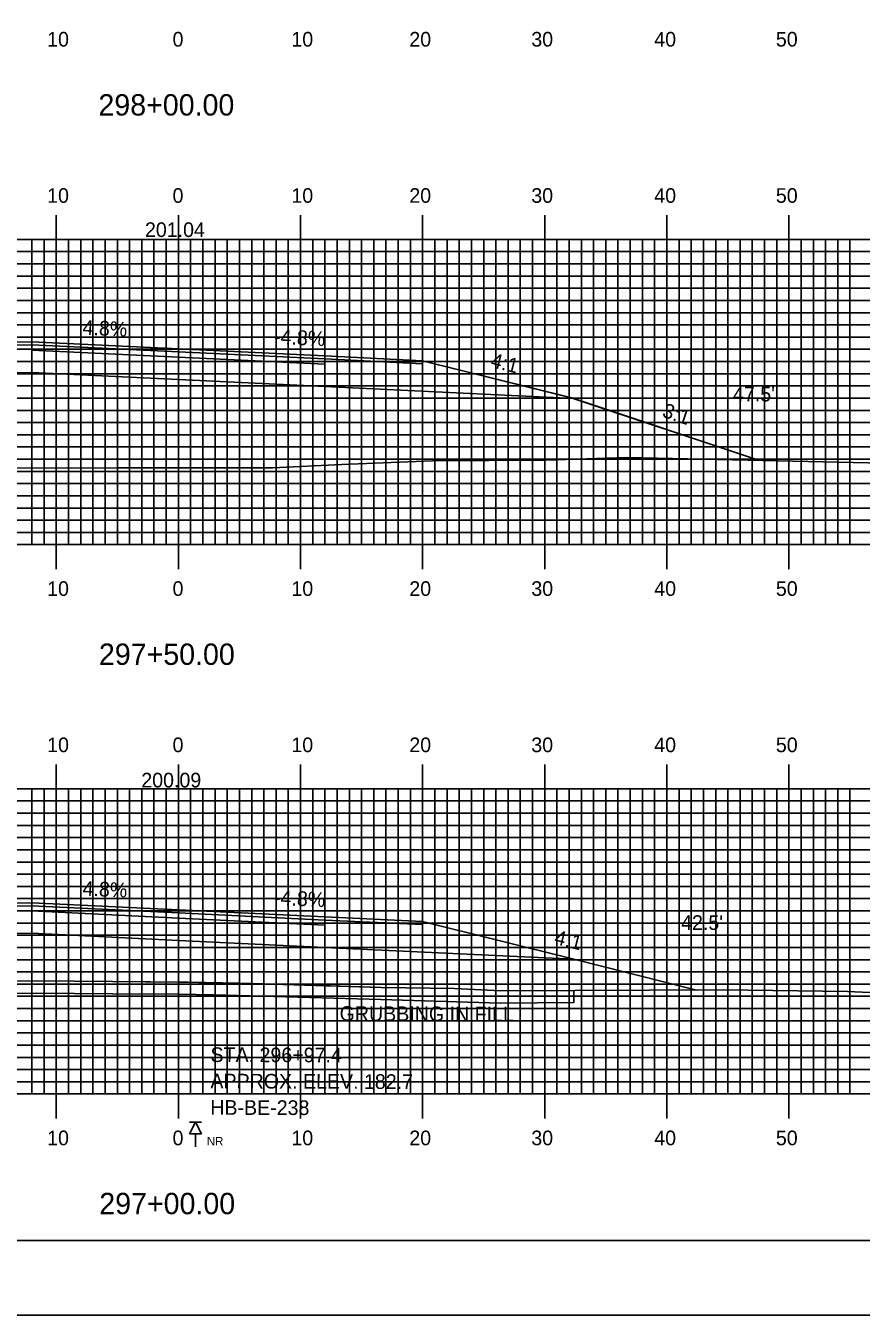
# Model space of a CAD drawing. Extents: x 1814915 to 1815259, y 442591 to 442811.
# Drawn here: x 1815068.5 to 1815136.9, y 442590.5 to 442696.2 of the extents above; entities that cross this region are included whole.
import ezdxf

# ---------------------------------------------------------------- set-up
doc = ezdxf.new("R2010")
doc.units = 0
for name, color, linetype in [('ANNOTATION', 7, 'Continuous'), ('BORDER', 7, 'Continuous'), ('BORING - NO REFUSAL', 7, 'Continuous'), ('D_Roadway_Centerline', 7, 'Continuous'), ('D_Roadway_Centerline_Text', 7, 'Continuous'), ('D_Roadway_Edge_Shoulder', 7, 'Continuous'), ('D_Roadway_Edge_TW', 7, 'Continuous'), ('D_Roadway_Pavement', 7, 'Continuous'), ('D_Roadway_SlopeLines', 7, 'Continuous'), ('D_Roadway_SubGrade', 7, 'Continuous'), ('D_Text_Standard', 7, 'Continuous'), ('GRUBBING IN FILL', 7, 'Continuous'), ('H_V ANNOTATION', 7, 'Continuous'), ('MAJOR', 7, 'Continuous'), ('MINOR', 7, 'Continuous'), ('PLOT BOUNDARY', 7, 'Continuous'), ('S_Roadway_Centerline', 7, 'Continuous')]:
    doc.layers.add(name, color=color, linetype=linetype)

msp = doc.modelspace()

# ---------------------------------------------------------------- linework, layer by layer
at = {"layer": 'BORDER'}
msp.add_lwpolyline([(1814931.42, 442596.67), (1815251.42, 442596.67), (1815251.42, 442806.67), (1814931.42, 442806.67)], close=True, dxfattribs=at)
at = {"layer": 'BORING - NO REFUSAL'}
for p, q in [((1815082.9, 442606.37), (1815081.94, 442606.37)), ((1815082.42, 442605.41), (1815082.42, 442604.35))]:
    msp.add_line(p, q, dxfattribs=at)
msp.add_lwpolyline([(1815082.42, 442606.37), (1815082.9, 442605.41), (1815081.94, 442605.41)], close=True, dxfattribs=at)
at = {"layer": 'D_Roadway_Centerline'}
for points in [[(1815026.39, 442659.58), (1815049.02, 442667.12), (1815050.15, 442667.4), (1815061.02, 442670.12), (1815069.02, 442670.28), (1815081.02, 442669.7), (1815093.02, 442669.13), (1815101.02, 442668.74), (1815113.02, 442665.74), (1815113.4, 442665.65), (1815128.52, 442660.58)], [(1815032.71, 442617.09), (1815049.02, 442621.17), (1815050.15, 442621.45), (1815061.02, 442624.17), (1815069.02, 442624.33), (1815081.02, 442623.75), (1815093.02, 442623.17), (1815101.02, 442622.79), (1815113.4, 442619.7), (1815123.45, 442617.18)]]:
    msp.add_lwpolyline(points, dxfattribs=at)
at = {"layer": 'D_Roadway_Edge_Shoulder'}
for points in [[(1815069.02, 442670.28), (1815061.02, 442670.12), (1815061.02, 442669.87), (1815069.02, 442670.03)], [(1815093.02, 442669.13), (1815101.02, 442668.74), (1815101.02, 442668.49), (1815093.02, 442668.88)], [(1815069.02, 442624.33), (1815061.02, 442624.17), (1815061.02, 442623.92), (1815069.02, 442624.08)], [(1815093.02, 442623.17), (1815101.02, 442622.79), (1815101.02, 442622.54), (1815093.02, 442622.92)]]:
    msp.add_lwpolyline(points, close=True, dxfattribs=at)
at = {"layer": 'D_Roadway_Edge_TW'}
for points in [[(1815069.02, 442670.03), (1815069.02, 442670.28), (1815081.02, 442669.7), (1815093.02, 442669.13), (1815093.02, 442668.88), (1815081.02, 442669.45)], [(1815069.02, 442624.08), (1815069.02, 442624.33), (1815081.02, 442623.75), (1815093.02, 442623.17), (1815093.02, 442622.92), (1815081.02, 442623.5)]]:
    msp.add_lwpolyline(points, close=True, dxfattribs=at)
at = {"layer": 'D_Roadway_Pavement'}
for points in [[(1815069.02, 442669.61), (1815069.02, 442670.03), (1815081.02, 442669.45), (1815093.02, 442668.88), (1815093.02, 442668.46), (1815081.02, 442669.04)], [(1815069.02, 442623.66), (1815069.02, 442624.08), (1815081.02, 442623.5), (1815093.02, 442622.92), (1815093.02, 442622.51), (1815081.02, 442623.08)]]:
    msp.add_lwpolyline(points, close=True, dxfattribs=at)
at = {"layer": 'D_Roadway_SlopeLines'}
for points in [[(1815101.02, 442668.74), (1815113.02, 442665.74), (1815128.52, 442660.58)], [(1815101.02, 442622.79), (1815113.4, 442619.7), (1815123.45, 442617.18)]]:
    msp.add_lwpolyline(points, dxfattribs=at)
at = {"layer": 'D_Roadway_SubGrade'}
for points in [[(1815069.02, 442667.78), (1815050.15, 442667.4), (1815061.02, 442670.12), (1815061.02, 442669.87), (1815069.02, 442670.03), (1815081.02, 442669.45), (1815093.02, 442668.88), (1815101.02, 442668.49), (1815101.02, 442668.74), (1815113.4, 442665.65), (1815093.02, 442666.63), (1815081.02, 442667.2)], [(1815069.02, 442621.83), (1815050.15, 442621.45), (1815061.02, 442624.17), (1815061.02, 442623.92), (1815069.02, 442624.08), (1815081.02, 442623.5), (1815093.02, 442622.92), (1815101.02, 442622.54), (1815101.02, 442622.79), (1815113.4, 442619.7), (1815093.02, 442620.67), (1815081.02, 442621.25)]]:
    msp.add_lwpolyline(points, close=True, dxfattribs=at)
at = {"layer": 'GRUBBING IN FILL'}
for points in [[(1815050.15, 442617.63), (1815052.24, 442617.71), (1815056.96, 442617.81), (1815064.58, 442617.9), (1815069.39, 442617.94), (1815075.61, 442617.88), (1815081.02, 442617.84), (1815081.02, 442616.84), (1815075.61, 442616.88), (1815069.39, 442616.94), (1815064.59, 442616.9), (1815056.98, 442616.81), (1815053.08, 442616.75), (1815050.15, 442616.59)], [(1815050.15, 442617.63), (1815052.24, 442617.71), (1815056.96, 442617.81), (1815064.58, 442617.9), (1815069.39, 442617.94), (1815075.61, 442617.88), (1815081.02, 442617.84), (1815081.02, 442616.84), (1815075.61, 442616.88), (1815069.39, 442616.94), (1815064.59, 442616.9), (1815056.98, 442616.81), (1815053.08, 442616.75), (1815050.15, 442616.59)], [(1815081.02, 442617.84), (1815086, 442617.75), (1815091.82, 442617.57), (1815097.63, 442617.4), (1815103.62, 442617.3), (1815107.42, 442617.12), (1815113.4, 442617.15), (1815113.4, 442616.15), (1815107.4, 442616.12), (1815097.61, 442616.4), (1815091.79, 442616.57), (1815083.9, 442616.79), (1815081.02, 442616.84)], [(1815081.02, 442617.84), (1815086, 442617.75), (1815091.82, 442617.57), (1815097.63, 442617.4), (1815103.62, 442617.3), (1815107.42, 442617.12), (1815113.4, 442617.15), (1815113.4, 442616.15), (1815107.4, 442616.12), (1815097.61, 442616.4), (1815091.79, 442616.57), (1815083.9, 442616.79), (1815081.02, 442616.84)]]:
    msp.add_lwpolyline(points, close=True, dxfattribs=at)
at = {"layer": 'MAJOR'}
for p, q in [((1815071.02, 442680.67), (1815071.02, 442678.67)), ((1815081.02, 442680.67), (1815081.02, 442678.67)), ((1815091.02, 442680.67), (1815091.02, 442678.67)), ((1815101.02, 442680.67), (1815101.02, 442678.67)), ((1815111.02, 442680.67), (1815111.02, 442678.67)), ((1815121.02, 442680.67), (1815121.02, 442678.67)), ((1815131.02, 442680.67), (1815131.02, 442678.67)), ((1814941.02, 442678.67), (1815221.02, 442678.67)), ((1814941.02, 442678.67), (1815221.02, 442678.67)), ((1815071.02, 442653.67), (1815071.02, 442678.67)), ((1815081.02, 442653.67), (1815081.02, 442678.67)), ((1815091.02, 442653.67), (1815091.02, 442678.67)), ((1815101.02, 442653.67), (1815101.02, 442678.67)), ((1815111.02, 442653.67), (1815111.02, 442678.67)), ((1815121.02, 442653.67), (1815121.02, 442678.67)), ((1815131.02, 442653.67), (1815131.02, 442678.67)), ((1814941.02, 442673.67), (1815221.02, 442673.67)), ((1814941.02, 442668.67), (1815221.02, 442668.67)), ((1814941.02, 442663.67), (1815221.02, 442663.67)), ((1814941.02, 442658.67), (1815221.02, 442658.67)), ((1814941.02, 442653.67), (1815221.02, 442653.67)), ((1814941.02, 442653.67), (1815221.02, 442653.67)), ((1815071.02, 442651.66), (1815071.02, 442653.67)), ((1815081.02, 442651.66), (1815081.02, 442653.67)), ((1815091.02, 442651.66), (1815091.02, 442653.67)), ((1815101.02, 442651.66), (1815101.02, 442653.67)), ((1815111.02, 442651.66), (1815111.02, 442653.67)), ((1815121.02, 442651.66), (1815121.02, 442653.67)), ((1815131.02, 442651.66), (1815131.02, 442653.67)), ((1815071.02, 442635.67), (1815071.02, 442633.67)), ((1815081.02, 442635.67), (1815081.02, 442633.67)), ((1815091.02, 442635.67), (1815091.02, 442633.67)), ((1815101.02, 442635.67), (1815101.02, 442633.67)), ((1815111.02, 442635.67), (1815111.02, 442633.67)), ((1815121.02, 442635.67), (1815121.02, 442633.67)), ((1815131.02, 442635.67), (1815131.02, 442633.67)), ((1814941.02, 442633.67), (1815221.02, 442633.67)), ((1814941.02, 442633.67), (1815221.02, 442633.67)), ((1815071.02, 442608.67), (1815071.02, 442633.67)), ((1815081.02, 442608.67), (1815081.02, 442633.67)), ((1815091.02, 442608.67), (1815091.02, 442633.67)), ((1815101.02, 442608.67), (1815101.02, 442633.67)), ((1815111.02, 442608.67), (1815111.02, 442633.67)), ((1815121.02, 442608.67), (1815121.02, 442633.67)), ((1815131.02, 442608.67), (1815131.02, 442633.67)), ((1814941.02, 442628.67), (1815221.02, 442628.67)), ((1814941.02, 442623.67), (1815221.02, 442623.67)), ((1814941.02, 442618.67), (1815221.02, 442618.67)), ((1814941.02, 442613.67), (1815221.02, 442613.67)), ((1814941.02, 442608.67), (1815221.02, 442608.67)), ((1814941.02, 442608.67), (1815221.02, 442608.67)), ((1815071.02, 442606.66), (1815071.02, 442608.67)), ((1815081.02, 442606.66), (1815081.02, 442608.67)), ((1815091.02, 442606.66), (1815091.02, 442608.67)), ((1815101.02, 442606.66), (1815101.02, 442608.67)), ((1815111.02, 442606.66), (1815111.02, 442608.67)), ((1815121.02, 442606.66), (1815121.02, 442608.67)), ((1815131.02, 442606.66), (1815131.02, 442608.67))]:
    msp.add_line(p, q, dxfattribs=at)
at = {"layer": 'MINOR'}
for p, q in [((1815069.02, 442653.67), (1815069.02, 442678.67)), ((1815070.02, 442653.67), (1815070.02, 442678.67)), ((1815072.02, 442653.67), (1815072.02, 442678.67)), ((1815073.02, 442653.67), (1815073.02, 442678.67)), ((1815074.02, 442653.67), (1815074.02, 442678.67)), ((1815075.02, 442653.67), (1815075.02, 442678.67)), ((1815076.02, 442653.67), (1815076.02, 442678.67)), ((1815077.02, 442653.67), (1815077.02, 442678.67)), ((1815078.02, 442653.67), (1815078.02, 442678.67)), ((1815079.02, 442653.67), (1815079.02, 442678.67)), ((1815080.02, 442653.67), (1815080.02, 442678.67)), ((1815082.02, 442653.67), (1815082.02, 442678.67)), ((1815083.02, 442653.67), (1815083.02, 442678.67)), ((1815084.02, 442653.67), (1815084.02, 442678.67)), ((1815085.02, 442653.67), (1815085.02, 442678.67)), ((1815086.02, 442653.67), (1815086.02, 442678.67)), ((1815087.02, 442653.67), (1815087.02, 442678.67)), ((1815088.02, 442653.67), (1815088.02, 442678.67)), ((1815089.02, 442653.67), (1815089.02, 442678.67)), ((1815090.02, 442653.67), (1815090.02, 442678.67)), ((1815092.02, 442653.67), (1815092.02, 442678.67)), ((1815093.02, 442653.67), (1815093.02, 442678.67)), ((1815094.02, 442653.67), (1815094.02, 442678.67)), ((1815095.02, 442653.67), (1815095.02, 442678.67)), ((1815096.02, 442653.67), (1815096.02, 442678.67)), ((1815097.02, 442653.67), (1815097.02, 442678.67)), ((1815098.02, 442653.67), (1815098.02, 442678.67)), ((1815099.02, 442653.67), (1815099.02, 442678.67)), ((1815100.02, 442653.67), (1815100.02, 442678.67)), ((1815102.02, 442653.67), (1815102.02, 442678.67)), ((1815103.02, 442653.67), (1815103.02, 442678.67)), ((1815104.02, 442653.67), (1815104.02, 442678.67)), ((1815105.02, 442653.67), (1815105.02, 442678.67)), ((1815106.02, 442653.67), (1815106.02, 442678.67)), ((1815107.02, 442653.67), (1815107.02, 442678.67)), ((1815108.02, 442653.67), (1815108.02, 442678.67)), ((1815109.02, 442653.67), (1815109.02, 442678.67)), ((1815110.02, 442653.67), (1815110.02, 442678.67)), ((1815112.02, 442653.67), (1815112.02, 442678.67)), ((1815113.02, 442653.67), (1815113.02, 442678.67)), ((1815114.02, 442653.67), (1815114.02, 442678.67)), ((1815115.02, 442653.67), (1815115.02, 442678.67)), ((1815116.02, 442653.67), (1815116.02, 442678.67)), ((1815117.02, 442653.67), (1815117.02, 442678.67)), ((1815118.02, 442653.67), (1815118.02, 442678.67)), ((1815119.02, 442653.67), (1815119.02, 442678.67)), ((1815120.02, 442653.67), (1815120.02, 442678.67)), ((1815122.02, 442653.67), (1815122.02, 442678.67)), ((1815123.02, 442653.67), (1815123.02, 442678.67)), ((1815124.02, 442653.67), (1815124.02, 442678.67)), ((1815125.02, 442653.67), (1815125.02, 442678.67)), ((1815126.02, 442653.67), (1815126.02, 442678.67)), ((1815127.02, 442653.67), (1815127.02, 442678.67)), ((1815128.02, 442653.67), (1815128.02, 442678.67)), ((1815129.02, 442653.67), (1815129.02, 442678.67)), ((1815130.02, 442653.67), (1815130.02, 442678.67)), ((1815132.02, 442653.67), (1815132.02, 442678.67)), ((1815133.02, 442653.67), (1815133.02, 442678.67)), ((1815134.02, 442653.67), (1815134.02, 442678.67)), ((1815135.02, 442653.67), (1815135.02, 442678.67)), ((1815136.02, 442653.67), (1815136.02, 442678.67)), ((1814941.02, 442677.67), (1815221.02, 442677.67)), ((1814941.02, 442676.67), (1815221.02, 442676.67)), ((1814941.02, 442675.67), (1815221.02, 442675.67)), ((1814941.02, 442674.67), (1815221.02, 442674.67)), ((1814941.02, 442672.67), (1815221.02, 442672.67)), ((1814941.02, 442671.67), (1815221.02, 442671.67)), ((1814941.02, 442670.67), (1815221.02, 442670.67)), ((1814941.02, 442669.67), (1815221.02, 442669.67)), ((1814941.02, 442667.67), (1815221.02, 442667.67)), ((1814941.02, 442666.67), (1815221.02, 442666.67)), ((1814941.02, 442665.67), (1815221.02, 442665.67)), ((1814941.02, 442664.67), (1815221.02, 442664.67)), ((1814941.02, 442662.67), (1815221.02, 442662.67)), ((1814941.02, 442661.67), (1815221.02, 442661.67)), ((1814941.02, 442660.67), (1815221.02, 442660.67)), ((1814941.02, 442659.67), (1815221.02, 442659.67)), ((1814941.02, 442657.67), (1815221.02, 442657.67)), ((1814941.02, 442656.67), (1815221.02, 442656.67)), ((1814941.02, 442655.67), (1815221.02, 442655.67)), ((1814941.02, 442654.67), (1815221.02, 442654.67)), ((1815069.02, 442608.67), (1815069.02, 442633.67)), ((1815070.02, 442608.67), (1815070.02, 442633.67)), ((1815072.02, 442608.67), (1815072.02, 442633.67)), ((1815073.02, 442608.67), (1815073.02, 442633.67)), ((1815074.02, 442608.67), (1815074.02, 442633.67)), ((1815075.02, 442608.67), (1815075.02, 442633.67)), ((1815076.02, 442608.67), (1815076.02, 442633.67)), ((1815077.02, 442608.67), (1815077.02, 442633.67)), ((1815078.02, 442608.67), (1815078.02, 442633.67)), ((1815079.02, 442608.67), (1815079.02, 442633.67)), ((1815080.02, 442608.67), (1815080.02, 442633.67)), ((1815082.02, 442608.67), (1815082.02, 442633.67)), ((1815083.02, 442608.67), (1815083.02, 442633.67)), ((1815084.02, 442608.67), (1815084.02, 442633.67)), ((1815085.02, 442608.67), (1815085.02, 442633.67)), ((1815086.02, 442608.67), (1815086.02, 442633.67)), ((1815087.02, 442608.67), (1815087.02, 442633.67)), ((1815088.02, 442608.67), (1815088.02, 442633.67)), ((1815089.02, 442608.67), (1815089.02, 442633.67)), ((1815090.02, 442608.67), (1815090.02, 442633.67)), ((1815092.02, 442608.67), (1815092.02, 442633.67)), ((1815093.02, 442608.67), (1815093.02, 442633.67)), ((1815094.02, 442608.67), (1815094.02, 442633.67)), ((1815095.02, 442608.67), (1815095.02, 442633.67)), ((1815096.02, 442608.67), (1815096.02, 442633.67)), ((1815097.02, 442608.67), (1815097.02, 442633.67)), ((1815098.02, 442608.67), (1815098.02, 442633.67)), ((1815099.02, 442608.67), (1815099.02, 442633.67)), ((1815100.02, 442608.67), (1815100.02, 442633.67)), ((1815102.02, 442608.67), (1815102.02, 442633.67)), ((1815103.02, 442608.67), (1815103.02, 442633.67)), ((1815104.02, 442608.67), (1815104.02, 442633.67)), ((1815105.02, 442608.67), (1815105.02, 442633.67)), ((1815106.02, 442608.67), (1815106.02, 442633.67)), ((1815107.02, 442608.67), (1815107.02, 442633.67)), ((1815108.02, 442608.67), (1815108.02, 442633.67)), ((1815109.02, 442608.67), (1815109.02, 442633.67)), ((1815110.02, 442608.67), (1815110.02, 442633.67)), ((1815112.02, 442608.67), (1815112.02, 442633.67)), ((1815113.02, 442608.67), (1815113.02, 442633.67)), ((1815114.02, 442608.67), (1815114.02, 442633.67)), ((1815115.02, 442608.67), (1815115.02, 442633.67)), ((1815116.02, 442608.67), (1815116.02, 442633.67)), ((1815117.02, 442608.67), (1815117.02, 442633.67)), ((1815118.02, 442608.67), (1815118.02, 442633.67)), ((1815119.02, 442608.67), (1815119.02, 442633.67)), ((1815120.02, 442608.67), (1815120.02, 442633.67)), ((1815122.02, 442608.67), (1815122.02, 442633.67)), ((1815123.02, 442608.67), (1815123.02, 442633.67)), ((1815124.02, 442608.67), (1815124.02, 442633.67)), ((1815125.02, 442608.67), (1815125.02, 442633.67)), ((1815126.02, 442608.67), (1815126.02, 442633.67)), ((1815127.02, 442608.67), (1815127.02, 442633.67)), ((1815128.02, 442608.67), (1815128.02, 442633.67)), ((1815129.02, 442608.67), (1815129.02, 442633.67)), ((1815130.02, 442608.67), (1815130.02, 442633.67)), ((1815132.02, 442608.67), (1815132.02, 442633.67)), ((1815133.02, 442608.67), (1815133.02, 442633.67)), ((1815134.02, 442608.67), (1815134.02, 442633.67)), ((1815135.02, 442608.67), (1815135.02, 442633.67)), ((1815136.02, 442608.67), (1815136.02, 442633.67)), ((1814941.02, 442632.67), (1815221.02, 442632.67)), ((1814941.02, 442631.67), (1815221.02, 442631.67)), ((1814941.02, 442630.67), (1815221.02, 442630.67)), ((1814941.02, 442629.67), (1815221.02, 442629.67)), ((1814941.02, 442627.67), (1815221.02, 442627.67)), ((1814941.02, 442626.67), (1815221.02, 442626.67)), ((1814941.02, 442625.67), (1815221.02, 442625.67)), ((1814941.02, 442624.67), (1815221.02, 442624.67)), ((1814941.02, 442622.67), (1815221.02, 442622.67)), ((1814941.02, 442621.67), (1815221.02, 442621.67)), ((1814941.02, 442620.67), (1815221.02, 442620.67)), ((1814941.02, 442619.67), (1815221.02, 442619.67)), ((1814941.02, 442617.67), (1815221.02, 442617.67)), ((1814941.02, 442616.67), (1815221.02, 442616.67)), ((1814941.02, 442615.67), (1815221.02, 442615.67)), ((1814941.02, 442614.67), (1815221.02, 442614.67)), ((1814941.02, 442612.67), (1815221.02, 442612.67)), ((1814941.02, 442611.67), (1815221.02, 442611.67)), ((1814941.02, 442610.67), (1815221.02, 442610.67)), ((1814941.02, 442609.67), (1815221.02, 442609.67))]:
    msp.add_line(p, q, dxfattribs=at)
at = {"layer": 'PLOT BOUNDARY'}
msp.add_lwpolyline([(1814915.23, 442590.55), (1815255.23, 442590.55), (1815255.23, 442810.55), (1814915.23, 442810.55)], close=True, dxfattribs=at)
at = {"layer": 'S_Roadway_Centerline'}
for points in [[(1815009.96, 442659.68), (1815019.41, 442659.59), (1815026, 442659.57), (1815036.63, 442659.78), (1815043.29, 442659.91), (1815058.79, 442659.92), (1815059.86, 442659.91), (1815065.31, 442659.94), (1815076.02, 442659.96), (1815088.76, 442659.95), (1815094.39, 442660.23), (1815101.84, 442660.54), (1815111.09, 442660.6), (1815117.76, 442660.81), (1815141.21, 442660.3)], [(1815010.86, 442616.56), (1815020.3, 442616.33), (1815025.82, 442616.72), (1815036.15, 442617.27), (1815051.44, 442617.66), (1815053.04, 442617.75), (1815054.16, 442617.77), (1815059.77, 442617.85), (1815069.39, 442617.94), (1815081.83, 442617.83), (1815086, 442617.75), (1815097.63, 442617.4), (1815103.62, 442617.3), (1815107.42, 442617.12), (1815125.62, 442617.19), (1815135.82, 442617.07), (1815152.82, 442616.3)]]:
    msp.add_lwpolyline(points, dxfattribs=at)

# ---------------------------------------------------------------- texts
at = {"layer": 'ANNOTATION'}
for s, rotation, p in [('4.8%', 357.2519, (1815073.15, 442670.88)), ('-4.8%', 357.2519, (1815088.83, 442670.13)), ('4:1', 345.9638, (1815106.53, 442668.23)), ('3:1', 341.4584, (1815120.57, 442664.16)), ('4.8%', 357.2519, (1815073.15, 442624.93)), ('-4.8%', 357.2519, (1815088.83, 442624.18)), ('4:1', 345.9638, (1815111.74, 442620.97))]:
    msp.add_text(s, height=1.2, rotation=rotation, dxfattribs=at).set_placement(p)
at = {"layer": 'BORING - NO REFUSAL'}
for s, p in [('STA. 296+97.4', (1815083.65, 442611.29)), ('APPROX. ELEV. 182.7', (1815083.64, 442609.13)), ('HB-BE-238', (1815083.63, 442606.97))]:
    msp.add_text(s, height=1.2, rotation=359.8142, dxfattribs=at).set_placement(p)
msp.add_text('NR', height=0.7, dxfattribs=at).set_placement((1815083.35, 442604.45))
at = {"layer": 'D_Roadway_Centerline'}
for s, p in [('C', (1815081.02, 442669.7)), ('L', (1815081.02, 442669.7)), ('C', (1815081.02, 442623.75)), ('L', (1815081.02, 442623.74))]:
    msp.add_text(s, height=0.0146, dxfattribs=at).set_placement(p)
at = {"layer": 'D_Roadway_Centerline_Text'}
for s, p in [('201.04', (1815078.28, 442678.87)), ('200.09', (1815077.98, 442633.78))]:
    msp.add_text(s, height=1.2, dxfattribs=at).set_placement(p)
at = {"layer": 'D_Text_Standard'}
for s, p in [("47.5'", (1815126.44, 442665.4)), ("42.5'", (1815122.19, 442622.11))]:
    msp.add_text(s, height=1.2, dxfattribs=at).set_placement(p)
at = {"layer": 'GRUBBING IN FILL'}
msp.add_text('GRUBBING IN FILL', height=1.2, rotation=359.8053, dxfattribs=at).set_placement((1815094.22, 442614.66))
at = {"layer": 'H_V ANNOTATION'}
for s, height, p in [('10', 1.2, (1815070.27, 442694.47)), ('0', 1.2, (1815080.54, 442694.47)), ('10', 1.2, (1815090.27, 442694.47)), ('20', 1.2, (1815099.93, 442694.47)), ('30', 1.2, (1815109.92, 442694.47)), ('40', 1.2, (1815119.99, 442694.47)), ('50', 1.2, (1815129.95, 442694.47)), ('298+00.00', 1.75, (1815074.47, 442688.82)), ('10', 1.2, (1815070.27, 442681.67)), ('0', 1.2, (1815080.54, 442681.67)), ('10', 1.2, (1815090.27, 442681.67)), ('20', 1.2, (1815099.93, 442681.67)), ('30', 1.2, (1815109.92, 442681.67)), ('40', 1.2, (1815119.99, 442681.67)), ('50', 1.2, (1815129.95, 442681.67)), ('10', 1.2, (1815070.27, 442649.47)), ('0', 1.2, (1815080.54, 442649.47)), ('10', 1.2, (1815090.27, 442649.47)), ('20', 1.2, (1815099.93, 442649.47)), ('30', 1.2, (1815109.92, 442649.47)), ('40', 1.2, (1815119.99, 442649.47)), ('50', 1.2, (1815129.95, 442649.47)), ('297+50.00', 1.75, (1815074.51, 442643.82)), ('10', 1.2, (1815070.27, 442636.67)), ('0', 1.2, (1815080.54, 442636.67)), ('10', 1.2, (1815090.27, 442636.67)), ('20', 1.2, (1815099.93, 442636.67)), ('30', 1.2, (1815109.92, 442636.67)), ('40', 1.2, (1815119.99, 442636.67)), ('50', 1.2, (1815129.95, 442636.67)), ('10', 1.2, (1815070.27, 442604.47)), ('0', 1.2, (1815080.54, 442604.47)), ('10', 1.2, (1815090.27, 442604.47)), ('20', 1.2, (1815099.93, 442604.47)), ('30', 1.2, (1815109.92, 442604.47)), ('40', 1.2, (1815119.99, 442604.47)), ('50', 1.2, (1815129.95, 442604.47)), ('297+00.00', 1.75, (1815074.54, 442598.82))]:
    msp.add_text(s, height=height, dxfattribs=at).set_placement(p)

doc.saveas('drawing.dxf')
